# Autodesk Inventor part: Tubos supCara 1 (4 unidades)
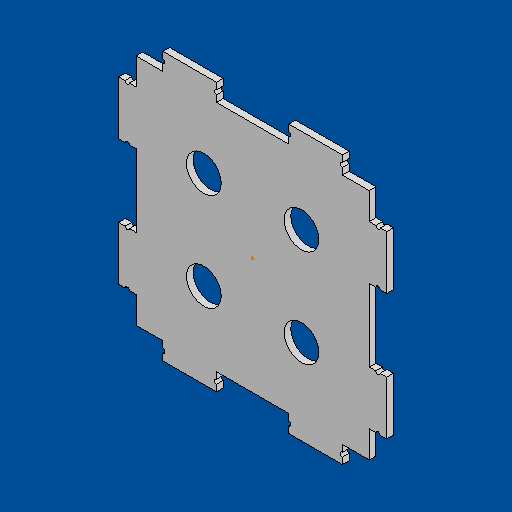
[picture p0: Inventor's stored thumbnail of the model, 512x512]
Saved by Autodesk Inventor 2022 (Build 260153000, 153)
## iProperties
Created: 2022-02
Part Number: Tubos supCara 1 (4 unidades)
Material: Genérico
Document SubType Name: Modeling
Designer: pined
Density: 1 g/cm^3
Appearance: Valor por defecto
Author: pined
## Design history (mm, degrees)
sketch "Boceto1"
  geometry: L1 (-50, -50)-(50, -50); L2 (50, -50)-(50, 50); L3 (50, 50)-(-50, 50); L4 (-50, 50)-(-50, -50); L5 (-50, -50)-(50, 50); L6 (50, -50)-(-50, 50); L7 (-44, 50)-(-44, 45); L8 (-44, 45)-(50, 45); L9 (50, 45)-(45, 45); L10 (-45, -45)-(45, -45); L11 (45, -45)-(45, 45); L12 (45, 45)-(-45, 45); L13 (-45, 45)-(-45, -45); L14 (-45, -45)-(45, 45); L15 (45, -45)-(-45, 45); L16 (-45, 45)-(-35, 45); L17 (-35, 45)-(-35, 50); L18 (-35, 50)-(-15, 50); L19 (-35, 45)-(-35, 47.5); L20 (-35, 47.5)-(-35, 48.3); L21 (-35, 49.1)-(-35, 50); L22 (-25, 50)-(-25, 45); L23 (-15, 45)-(-15, 47.5); L24 (-15, 45)-(-15, 50); L25 (-15, 49.1)-(-15, 50); L26 (-15, 49.1)-(-15, 50.122); L27 (0, 21)-(0, -12); L28 (-10, 0)-(12, 0); L29 (35, 45)-(35, 47.5); L30 (35, 45)-(35, 50); L31 (35, 49.1)-(35, 50); L32 (15, 45)-(15, 50); L33 (15, 45)-(15, 47.5); L34 (15, 49.1)-(15, 50.122); L35 (35, 50)-(15, 50); L36 (-35, -45)-(-35, -50); L37 (-35, -45)-(-35, -47.5); L38 (-35, -49.1)-(-35, -50); L39 (50, -50)-(-50, -50); L40 (-35, -50)-(-15, -50); L41 (-15, -49.1)-(-15, -50.122); L42 (-15, -45)-(-15, -47.5); L43 (15, -45)-(15, -50); L44 (15, -45)-(15, -47.5); L45 (15, -49.1)-(15, -50.122); L46 (35, -50)-(15, -50); L47 (35, -45)-(35, -50); L48 (35, -45)-(35, -47.5); L49 (35, -49.1)-(35, -50); L50 (-45, -35)-(-50, -35); L51 (-49.1, -35)-(-50, -35); L52 (-45, -35)-(-47.5, -35); L53 (-50, 50)-(-50, -50); L54 (-50, -35)-(-50, -15); L55 (-49.1, -15)-(-50.122, -15); L56 (-45, -15)-(-47.5, -15); L57 (-45, 35)-(-50, 35); L58 (-45, 35)-(-47.5, 35); L59 (-49.1, 35)-(-50, 35); L60 (-45, 15)-(-47.5, 15); L61 (-45, 15)-(-50, 15); L62 (-49.1, 15)-(-50.122, 15); L63 (-50, 35)-(-50, 15); L64 (35, -45)-(35, -50)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; A1 r 0.8 centre (-35, 48.3) between (-35, 49.1) and (-35, 47.5); A2 r 0.8 centre (-35, 48.3) between (-35, 47.5) and (-35, 49.1); A3 r 0.8 centre (-15, 48.3) between (-15, 49.1) and (-15, 47.5); A4 r 0.8 centre (35, 48.3) between (35, 49.1) and (35, 47.5); A5 r 0.8 centre (15, 48.3) between (15, 47.5) and (15, 49.1); A6 r 0.8 centre (-35, -48.3) between (-35, -49.1) and (-35, -47.5); A7 r 0.8 centre (-15, -48.3) between (-15, -47.5) and (-15, -49.1); A8 r 0.8 centre (15, -48.3) between (15, -49.1) and (15, -47.5); A9 r 0.8 centre (35, -48.3) between (35, -47.5) and (35, -49.1); A10 r 0.8 centre (-48.3, -35) between (-47.5, -35) and (-49.1, -35); A11 r 0.8 centre (-48.3, -15) between (-49.1, -15) and (-47.5, -15); A12 r 0.8 centre (-48.3, 35) between (-49.1, 35) and (-47.5, 35); A13 r 0.8 centre (-48.3, 15) between (-47.5, 15) and (-49.1, 15); A14 r 0.8 centre (35, -48.3) between (35, -47.5) and (35, -49.1); A15 r 0.8 centre (15, -48.3) between (15, -49.1) and (15, -47.5); A16 r 0.8 centre (-35, -48.3) between (-35, -49.1) and (-35, -47.5); A17 r 0.8 centre (-15, -48.3) between (-15, -47.5) and (-15, -49.1); A18 r 0.8 centre (48.3, 35) between (47.5, 35) and (49.1, 35); A19 r 0.8 centre (48.3, 15) between (49.1, 15) and (47.5, 15); A20 r 0.8 centre (48.3, -35) between (49.1, -35) and (47.5, -35); A21 r 0.8 centre (48.3, -15) between (47.5, -15) and (49.1, -15); 22 further points
  constraints: 206 end point, 42 point on circle, 39 point on line, 37 symmetric about line, 21 centre point, 21 midpoint, 8 perpendicular, 5 parallel, 4 coincident, 3 horizontal, 2 collinear, 1 vertical, 143 other
  dimensions: "d0" = 100 distance of L3.end L2.end; "d1" = 100 distance of L2.end L1.end; "d3" = 5 distance of L8.end L9.end; "d4" = 10 distance of L12.end L16.end; "d5" = 20 distance of L17.end L18.end; "d6" = 2.5 distance of L16.end L19.end; "d7" = 0.8 distance of L19.end L20.end; "d10" = 270 deg dimension on point (0, 0) A1.centre A18.centre; "d24" = 90 distance between parallel lines of L10 L12 (derived)
extrude "Extrusión1" new body sketch "Boceto1" distance "d12" = 2.5; taper "d13" = 0 deg
sketch "Boceto2"
  geometry: 1 further point
sketch "Sketch4"
  geometry: L1 (-43.5, -43.5)-(43.5, -43.5); L2 (43.5, -43.5)-(43.5, 43.5); L3 (43.5, 43.5)-(-43.5, 43.5); L4 (-43.5, 43.5)-(-43.5, -43.5); L5 (-43.5, -43.5)-(43.5, 43.5); L6 (43.5, -43.5)-(-43.5, 43.5); L7 (-35, 45)-(-35, 43.5); L8 (-35, 47.5)-(-35, 45) reference; L9 (-35, 45)-(-45, 45) reference; L10 (-45, 45)-(-45, 35) reference; L11 (-45, 35)-(-47.5, 35) reference; L12 (-49.1, 35)-(-50, 35) reference; L13 (-50, 35)-(-50, 15) reference; L14 (-50, 15)-(-49.1, 15) reference; L15 (-47.5, 15)-(-45, 15) reference; L16 (-45, 15)-(-45, -15) reference; L17 (-45, -15)-(-47.5, -15) reference; L18 (-49.1, -15)-(-50, -15) reference; L19 (-50, -15)-(-50, -35) reference; L20 (-50, -35)-(-49.1, -35) reference; L21 (-47.5, -35)-(-45, -35) reference; L22 (-45, -35)-(-45, -45) reference; L23 (-45, -45)-(-35, -45) reference; L24 (-35, -45)-(-35, -47.5) reference; L25 (-35, -49.1)-(-35, -50) reference; L26 (-35, -50)-(-15, -50) reference; L27 (-15, -50)-(-15, -49.1) reference; L28 (-15, -47.5)-(-15, -45) reference; L29 (-15, -45)-(15, -45) reference; L30 (15, -45)-(15, -47.5) reference; L31 (15, -49.1)-(15, -50) reference; L32 (15, -50)-(35, -50) reference; L33 (35, -50)-(35, -49.1) reference; L34 (35, -47.5)-(35, -45) reference; L35 (35, -45)-(45, -45) reference; L36 (45, -45)-(45, -35) reference; L37 (45, -35)-(47.5, -35) reference; L38 (49.1, -35)-(50, -35) reference; L39 (50, -35)-(50, -15) reference; L40 (50, -15)-(49.1, -15) reference; L41 (47.5, -15)-(45, -15) reference; L42 (45, -15)-(45, 15) reference; L43 (45, 15)-(47.5, 15) reference; L44 (49.1, 15)-(50, 15) reference; L45 (50, 15)-(50, 35) reference; L46 (50, 35)-(49.1, 35) reference; L47 (47.5, 35)-(45, 35) reference; L48 (45, 35)-(45, 45) reference; L49 (45, 45)-(35, 45) reference; L50 (35, 45)-(35, 47.5) reference; L51 (35, 49.1)-(35, 50) reference; L52 (35, 50)-(15, 50) reference; L53 (15, 50)-(15, 49.1) reference; L54 (15, 47.5)-(15, 45) reference; L55 (15, 45)-(-15, 45) reference; L56 (-15, 45)-(-15, 47.5) reference; L57 (-15, 49.1)-(-15, 50) reference; L58 (-15, 50)-(-35, 50) reference; L59 (-35, 50)-(-35, 49.1) reference; L60 (-45, 45)-(-45, 35) reference; L61 (-45, 35)-(-43.5, 35); L62 (-47.5, 15)-(-45, 15) reference; L63 (-45, 15)-(-43.5, 15); L64 (-45, 15)-(-45, -15) reference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; A1 r 0.8 centre (-35, 48.3) between (-35, 47.5) and (-35, 49.1) reference; A2 r 0.8 centre (-48.3, 35) between (-49.1, 35) and (-47.5, 35) reference; A3 r 0.8 centre (-48.3, 15) between (-47.5, 15) and (-49.1, 15) reference; A4 r 0.8 centre (-48.3, -15) between (-49.1, -15) and (-47.5, -15) reference; A5 r 0.8 centre (-48.3, -35) between (-47.5, -35) and (-49.1, -35) reference; A6 r 0.8 centre (-35, -48.3) between (-35, -49.1) and (-35, -47.5) reference; A7 r 0.8 centre (-15, -48.3) between (-15, -47.5) and (-15, -49.1) reference; A8 r 0.8 centre (15, -48.3) between (15, -49.1) and (15, -47.5) reference; A9 r 0.8 centre (35, -48.3) between (35, -47.5) and (35, -49.1) reference; A10 r 0.8 centre (48.3, -35) between (49.1, -35) and (47.5, -35) reference; A11 r 0.8 centre (48.3, -15) between (47.5, -15) and (49.1, -15) reference; A12 r 0.8 centre (48.3, 15) between (49.1, 15) and (47.5, 15) reference; A13 r 0.8 centre (48.3, 35) between (47.5, 35) and (49.1, 35) reference; A14 r 0.8 centre (35, 48.3) between (35, 49.1) and (35, 47.5) reference; A15 r 0.8 centre (15, 48.3) between (15, 47.5) and (15, 49.1) reference; A16 r 0.8 centre (-15, 48.3) between (-15, 49.1) and (-15, 47.5) reference; 2 further points
  constraints: 44 end point, 19 point on line, 13 perpendicular, 2 midpoint, 2 parallel, 1 horizontal, 1 vertical
  dimensions: "d25" = 87 distance of L3.end L2.end; "d26" = 87 distance of L2.end L1.end
extrude "Extrusion3" cut sketch "Sketch4" distance "d27" = 10; taper "d28" = 0 deg
sketch "Sketch5"
  geometry: L1 (-49.1, 35)-(-47.5, 35); L2 (-47.5, 35)-(-43.5, 35) reference; L3 (-50, 35)-(-50, 15) reference; L4 (-43.5, 35)-(-50, 35); L5 (-50, 35)-(-50, 15); L6 (-50, 15)-(-43.5, 15); L7 (-43.5, 15)-(-43.5, 35); L8 (-15, 50)-(-35, 50) reference; L9 (-35, 43.5)-(-43.5, 43.5) reference; L10 (-15, 50)-(-35, 50); L11 (-35, 50)-(-35, 43.5); L12 (-35, 43.5)-(-15, 43.5); L13 (-15, 43.5)-(-15, 50); L14 (15, 47.5)-(15, 43.5) reference; L15 (35, 50)-(15, 50) reference; L16 (15, 43.5)-(35, 43.5); L17 (35, 43.5)-(35, 50); L18 (35, 50)-(15, 50); L19 (15, 50)-(15, 43.5); L20 (47.5, 35)-(43.5, 35) reference; L21 (49.1, 15)-(50, 15) reference; L22 (43.5, 35)-(50, 35); L23 (50, 35)-(50, 15); L24 (50, 15)-(43.5, 15); L25 (43.5, 15)-(43.5, 35); L26 (47.5, -15)-(43.5, -15) reference; L27 (43.5, -15)-(50, -15); L28 (50, -15)-(50, -35); L29 (50, -35)-(43.5, -35); L30 (43.5, -35)-(43.5, -15); L31 (35, -43.5)-(43.5, -43.5) reference; L32 (15, -50)-(35, -50) reference; L33 (35, -43.5)-(15, -43.5); L34 (15, -43.5)-(15, -50); L35 (15, -50)-(35, -50); L36 (35, -50)-(35, -43.5); L37 (-15, -43.5)-(15, -43.5) reference; L38 (-35, -50)-(-15, -50) reference; L39 (-15, -43.5)-(-35, -43.5); L40 (-35, -43.5)-(-35, -50); L41 (-35, -50)-(-15, -50); L42 (-15, -50)-(-15, -43.5); L43 (-47.5, -35)-(-43.5, -35) reference; L44 (-49.1, -15)-(-50, -15) reference; L45 (-43.5, -35)-(-50, -35); L46 (-50, -35)-(-50, -15); L47 (-50, -15)-(-43.5, -15); L48 (-43.5, -15)-(-43.5, -35); A1 r 0.8 centre (-48.3, 35) between (-49.1, 35) and (-47.5, 35) reference; 13 further points
  constraints: 66 end point, 16 parallel, 9 horizontal, 8 perpendicular, 1 point on line
extrude "Extrusion4" join sketch "Sketch5" distance "d29" = 2.5; taper "d30" = 0 deg
sketch "Sketch6"
  geometry: L1 (-35, 43.5)-(-35, 46.8); L2 (-35, 50)-(-35, 43.5) reference; L3 (-35, 46.8)-(40.671, 46.8); L4 (35, 43.5)-(35, 50) reference; L5 (-15, 43.5)-(-15, 50) reference; L6 (15, 50)-(15, 43.5) reference; L7 (0, 0)-(22.296, 0); L8 (-43.5, 35)-(-46.8, 35); L9 (-43.5, 35)-(-50, 35) reference; L10 (-46.8, 35)-(-46.8, -41.122); L11 (-50, 15)-(-43.5, 15) reference; L12 (-43.5, -15)-(-50, -15) reference; L13 (-50, -35)-(-43.5, -35) reference; L14 (0, 0)-(0, 10.489); C1 r 0.8 at (-35, 46.8); C2 r 0.8 at (-15, 46.75); C3 r 0.8 at (15, 46.75); C4 r 0.8 at (35, 46.75); C5 r 0.8 at (-15, -46.75); C6 r 0.8 at (-35, -46.8); C7 r 0.8 at (15, -46.75); C8 r 0.8 at (35, -46.75); C9 r 0.8 at (-46.8, 35); C10 r 0.8 at (-46.75, 15); C11 r 0.8 at (-46.75, -15); C12 r 0.8 at (-46.75, -35); C13 r 0.8 at (46.8, 35); C14 r 0.8 at (46.75, 15); C15 r 0.8 at (46.75, -15); C16 r 0.8 at (46.75, -35); 4 further points
  constraints: 16 centre point, 12 end point, 8 symmetric about line, 6 midpoint, 2 coincident, 2 perpendicular, 2 point on line, 1 horizontal, 1 vertical, 8 other
  dimensions: "d31" = 3.3 distance of L1.start L1.end; "d32" = 1.6 diameter of C1; "d33" = 1.6 diameter of C2; "d34" = 1.6 diameter of C3; "d35" = 1.6 diameter of C4; "d36" = 3.3 distance of L8.start L8.end; "d37" = 1.6 diameter of C9; "d38" = 1.6 diameter of C10; "d39" = 1.6 diameter of C11; "d40" = 1.6 diameter of C12
extrude "Extrusion5" cut sketch "Sketch6" distance "d41" = 2.5; taper "d42" = 0 deg
sketch "Sketch7"
  geometry: L1 (-35, 43.5)-(-43.5, 43.5) reference; L2 (-35, 50)-(-15, 50) reference; L3 (-43.5, 43.5)-(-33.5, 43.5); L4 (-33.5, 43.5)-(-33.5, 50); L5 (-33.5, 50)-(-43.5, 50); L6 (-43.5, 50)-(-43.5, 43.5); L7 (15, 50)-(35, 50) reference; L8 (43.5, 43.5)-(33.5, 43.5); L9 (33.5, 43.5)-(33.5, 50); L10 (33.5, 50)-(43.5, 50); L11 (43.5, 50)-(43.5, 43.5); L12 (-50, 15)-(-50, 35) reference; L13 (-43.5, 43.5)-(-50, 43.5); L14 (-50, 43.5)-(-50, 33.5); L15 (-50, 33.5)-(-43.5, 33.5); L16 (-43.5, 33.5)-(-43.5, 43.5); L17 (-43.5, -43.5)-(-35, -43.5) reference; L18 (-50, -35)-(-50, -15) reference; L19 (-43.5, -43.5)-(-50, -43.5); L20 (-50, -43.5)-(-50, -33.5); L21 (-50, -33.5)-(-43.5, -33.5); L22 (-43.5, -33.5)-(-43.5, -43.5); L23 (-43.5, -43.5)-(-33.5, -43.5); L24 (-33.5, -43.5)-(-33.5, -50); L25 (-33.5, -50)-(-43.5, -50); L26 (-43.5, -50)-(-43.5, -43.5); L27 (43.5, -43.5)-(43.5, -35) reference; L28 (35, -50)-(15, -50) reference; L29 (43.5, -43.5)-(33.5, -43.5); L30 (33.5, -43.5)-(33.5, -50); L31 (33.5, -50)-(43.5, -50); L32 (43.5, -50)-(43.5, -43.5); L33 (50, -15)-(50, -35) reference; L34 (43.5, -43.5)-(50, -43.5); L35 (50, -43.5)-(50, -33.5); L36 (50, -33.5)-(43.5, -33.5); L37 (43.5, -33.5)-(43.5, -43.5); L38 (50, 35)-(50, 15) reference; L39 (43.5, 43.5)-(50, 43.5); L40 (50, 43.5)-(50, 33.5); L41 (50, 33.5)-(43.5, 33.5); L42 (43.5, 33.5)-(43.5, 43.5); 11 further points
  constraints: 64 end point, 16 parallel, 8 horizontal, 8 perpendicular, 7 point on line
  dimensions: "d43" = 10 distance of L5.end L4.end; "d44" = 10 distance of L9.end L10.end; "d45" = 10 distance of L14.end L13.end; "d46" = 10 distance of L19.end L20.end; "d47" = 6.5 distance of L23.end L24.end; "d48" = 10 distance of L31.end L30.end; "d49" = 10 distance of L35.end L34.end; "d50" = 10 distance of L39.end L40.end
extrude "Extrusion6" cut sketch "Sketch7" distance "d51" = 10; taper "d52" = 0 deg
sketch "Sketch8"
  geometry: L1 (-33.5, 50)-(-15, 50) reference; L2 (-15, 43.5)-(15, 43.5) reference; L3 (-33.5, 50)-(-13.5, 50); L4 (-13.5, 50)-(-13.5, 43.5); L5 (-13.5, 43.5)-(-33.5, 43.5); L6 (-33.5, 43.5)-(-33.5, 50); L7 (15, 50)-(33.5, 50) reference; L8 (33.5, 50)-(13.5, 50); L9 (13.5, 50)-(13.5, 43.5); L10 (13.5, 43.5)-(33.5, 43.5); L11 (33.5, 43.5)-(33.5, 50); L12 (50, 33.5)-(50, 15) reference; L13 (43.5, -15)-(43.5, 15) reference; L14 (50, 33.5)-(43.5, 33.5); L15 (43.5, 33.5)-(43.5, 13.5); L16 (43.5, 13.5)-(50, 13.5); L17 (50, 13.5)-(50, 33.5); L18 (50, -15)-(50, -33.5) reference; L19 (50, -33.5)-(43.5, -33.5); L20 (43.5, -33.5)-(43.5, -13.5); L21 (43.5, -13.5)-(50, -13.5); L22 (50, -13.5)-(50, -33.5); L23 (33.5, -43.5)-(43.5, -43.5) reference; L24 (33.5, -43.5)-(13.5, -43.5); L25 (13.5, -43.5)-(13.5, -50); L26 (13.5, -50)-(33.5, -50); L27 (33.5, -50)-(33.5, -43.5); L28 (-43.5, -43.5)-(-33.5, -43.5) reference; L29 (-33.5, -43.5)-(-13.5, -43.5); L30 (-13.5, -43.5)-(-13.5, -50); L31 (-13.5, -50)-(-33.5, -50); L32 (-33.5, -50)-(-33.5, -43.5); L33 (-50, -33.5)-(-43.5, -33.5) reference; L34 (-43.5, 15)-(-43.5, -15) reference; L35 (-50, -33.5)-(-43.5, -33.5); L36 (-43.5, -33.5)-(-43.5, -13.5); L37 (-43.5, -13.5)-(-50, -13.5); L38 (-50, -13.5)-(-50, -33.5); L39 (-50, 15)-(-50, 33.5) reference; L40 (-50, 33.5)-(-43.5, 33.5); L41 (-43.5, 33.5)-(-43.5, 13.5); L42 (-43.5, 13.5)-(-50, 13.5); L43 (-50, 13.5)-(-50, 33.5); 16 further points
  constraints: 64 end point, 16 parallel, 8 horizontal, 8 perpendicular, 6 point on line
  dimensions: "d53" = 20 distance of L4.end L5.end; "d54" = 20 distance of L10.end L9.end; "d55" = 20 distance of L15.end L14.end; "d56" = 6.5 distance of L20.end L21.end; "d57" = 20 distance of L19.end L20.end; "d58" = 20 distance of L26.end L25.end; "d59" = 20 distance of L30.end L31.end; "d60" = 20 distance of L36.end L35.end; "d61" = 20 distance of L40.end L41.end
extrude "Extrusion7" join sketch "Sketch8" distance "d62" = 2.5; taper "d63" = 0 deg
sketch "Sketch9"
  geometry: L1 (-33.5, 50)-(-33.5, 43.5) reference; L2 (-33.5, 43.5)-(-33.5, 46.8); L3 (-33.5, 46.8)-(40.435, 46.8); L4 (-43.5, 43.5)-(-43.5, 33.5) reference; L5 (-43.5, 33.5)-(-46.8, 33.5); L6 (-43.5, 33.5)-(-50, 33.5) reference; L7 (-46.8, 33.5)-(-46.8, -49.655); L8 (33.5, 43.5)-(33.5, 50) reference; L9 (13.5, 50)-(13.5, 43.5) reference; L10 (-13.5, 50)-(-13.5, 43.5) reference; L11 (-43.5, 13.5)-(-50, 13.5) reference; L12 (-43.5, -13.5)-(-50, -13.5) reference; L13 (-43.5, -33.5)-(-50, -33.5) reference; L14 (0, 0)-(13.5, 0); L15 (13.5, 0)-(0, 0); L16 (0, 0)-(0, 17.379); C1 r 0.8 at (33.5, 46.75); C2 r 0.8 at (13.5, 46.75); C3 r 0.8 at (-13.5, 46.75); C4 r 0.8 at (-33.5, 46.8); C5 r 0.8 at (-46.8, 33.5); C6 r 0.8 at (-46.75, 13.5); C7 r 0.8 at (-46.75, -13.5); C8 r 0.8 at (-46.75, -33.5); C9 r 0.8 at (-33.5, -46.8); C10 r 0.8 at (-13.5, -46.75); C11 r 0.8 at (13.5, -46.75); C12 r 0.8 at (33.5, -46.75); C13 r 0.8 at (46.8, 33.5); C14 r 0.8 at (46.75, 13.5); C15 r 0.8 at (46.75, -13.5); C16 r 0.8 at (46.75, -33.5); 10 further points
  constraints: 16 centre point, 14 end point, 8 symmetric about line, 6 midpoint, 2 coincident, 2 perpendicular, 2 point on line, 1 collinear, 1 horizontal, 1 vertical, 8 other
  dimensions: "d64" = 3.3 distance of L1.end L2.end; "d65" = 3.3 distance of L4.end L5.end; "d66" = 1.6 diameter of C1; "d67" = 1.6 diameter of C2; "d68" = 1.6 diameter of C3; "d69" = 1.6 diameter of C4; "d70" = 1.6 diameter of C5; "d71" = 1.6 diameter of C6; "d72" = 1.6 diameter of C7; "d73" = 1.6 diameter of C8
extrude "Extrusion8" cut sketch "Sketch9" distance "d74" = 2.5; taper "d75" = 0 deg
sketch "Sketch10"
  geometry: L1 (43.5, 43.5)-(33.5, 43.5) reference; L2 (-43.5, -43.5)-(43.5, -43.5); L3 (43.5, -43.5)-(43.5, 43.5); L4 (43.5, 43.5)-(-43.5, 43.5); L5 (-43.5, 43.5)-(-43.5, -43.5); L6 (-43.5, -43.5)-(43.5, 43.5); L7 (43.5, -43.5)-(-43.5, 43.5); L8 (43.5, 43.5)-(43.5, 33.5) reference; L9 (43.5, 43.5)-(0, 0); L10 (-43.5, -43.5)-(-33.5, -43.5) reference; L11 (0, 0)-(-43.5, -43.5); L12 (-33.5, 43.5)-(-43.5, 43.5) reference; L13 (-43.5, 43.5)-(0, 0); L14 (33.5, -43.5)-(43.5, -43.5) reference; L15 (0, 0)-(43.5, -43.5); L16 (-21.75, -21.75)-(-18.214, -18.214); L17 (21.75, -21.75)-(18.214, -18.214); L18 (-21.75, 21.75)-(-18.214, 18.214); L19 (21.75, 21.75)-(18.214, 18.214); C1 r 6.5 at (-18.214, 18.214); C2 r 6.5 at (18.214, 18.214); C3 r 6.5 at (-18.214, -18.214); C4 r 6.5 at (18.214, -18.214)
  constraints: 28 end point, 6 midpoint, 5 point on line, 4 centre point, 4 equal length, 3 coincident, 2 perpendicular, 1 horizontal
  dimensions: "d76" = 5 distance of L16.start L16.end; "d77" = 5 distance of L17.start L17.end; "d78" = 5 distance of L18.start L18.end; "d79" = 5 distance of L19.start L19.end; "d80" = 13 diameter of C1; "d81" = 13 diameter of C2; "d82" = 13 diameter of C3; "d83" = 13 diameter of C4
extrude "Extrusion9" cut sketch "Sketch10" distance "d84" = 2.5; taper "d85" = 0 deg
node "Sólido1"
node "Projected Loop1"
